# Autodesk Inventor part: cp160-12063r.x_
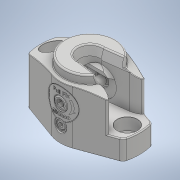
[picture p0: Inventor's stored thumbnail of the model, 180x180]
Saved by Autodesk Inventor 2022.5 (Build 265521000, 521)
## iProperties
Created: 2019-12
Part Number: cp160-12063r.x_
Material: 一般
Document SubType Name: Modeling
Designer: ImaoCorp
Density: 1 g/cm^3
Appearance: 既定
Sending System: SOLIDWORKS 2018-2018316
MC: AMD64
MC_MODEL: Intel64 Family 6 Model 60 Stepping 3, GenuineIntel
OS: Windows_NT
FRU: Parasolid Version 30.0, build 310,  6- 8-2018
FORMAT: text
GUISE: transmit
KEY: cp160-12063r
FILE: cp160-12063r.x_t
DATE: Wed Dec 11 13:10:50 2019
Author: ImaoCorp
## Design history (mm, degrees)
feature "Base1"
node "ソリッド1"
